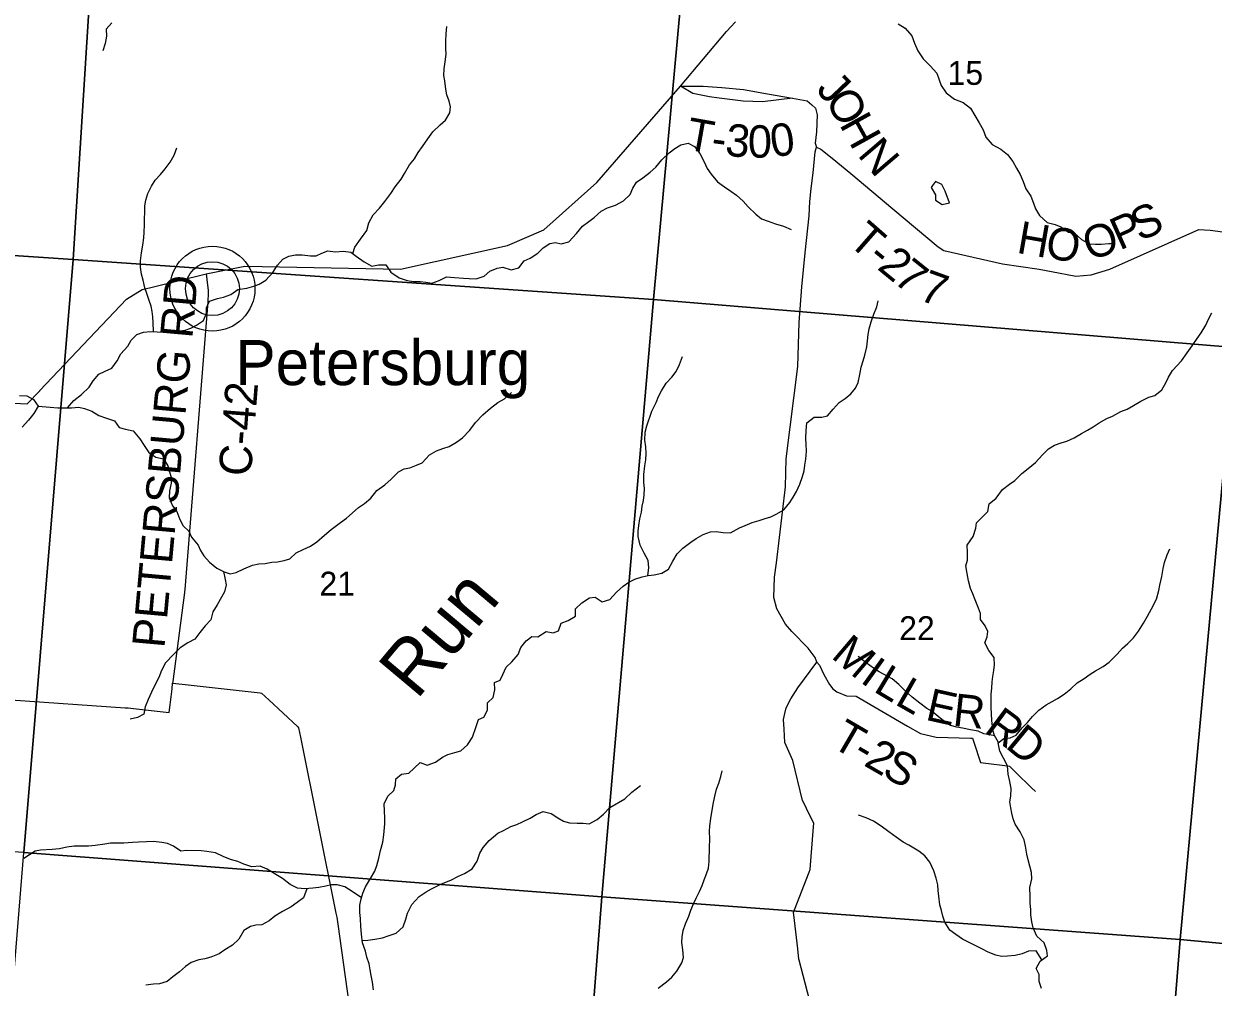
# Model space of a CAD drawing. Extents: x 1715311 to 2083412, y 146837 to 553079.
# Drawn here: x 1897277 to 1908281, y 354105 to 363016 of the extents above; entities that cross this region are included whole.
import ezdxf

# ---------------------------------------------------------------- set-up
doc = ezdxf.new("R2010")
doc.units = 0
for name, color, linetype in [('GM_X_County_Road', 7, 'Continuous'), ('GM_X_County_Road_Text', 7, 'Continuous'), ('GM_X_Minor_Lake', 7, 'Continuous'), ('GM_X_Minor_River', 7, 'Continuous'), ('GM_X_Minor_River_Text', 7, 'Continuous'), ('GM_X_Section', 7, 'Continuous'), ('GM_X_Section_Text', 7, 'Continuous'), ('GM_X_State_Route', 7, 'Continuous'), ('GM_X_Township_Road', 7, 'Continuous'), ('GM_X_Township_Road_Text', 7, 'Continuous'), ('GM_X_Township_ROW', 7, 'Continuous'), ('GM_X_Unincorporated', 7, 'Continuous'), ('GM_X_Unincorporated_Location', 7, 'Continuous'), ('GM_X_Unincorporated_Text', 7, 'Continuous')]:
    doc.layers.add(name, color=color, linetype=linetype)

msp = doc.modelspace()

# ---------------------------------------------------------------- linework, layer by layer
at = {"layer": 'GM_X_County_Road'}
msp.add_lwpolyline([(1898963, 360703), (1898969, 360652), (1898981, 360549), (1898984, 360524), (1898978, 360445), (1898773, 357859), (1898770, 357819), (1898762, 357755), (1898656, 356932), (1898654, 356916), (1898741, 356907), (1899464, 356828), (1899477, 356826), (1899543, 356764), (1899808, 356516), (1899819, 356505), (1899837, 356419), (1900165, 354791), (1900172, 354754), (1900181, 354688), (1900404, 353095)], dxfattribs=at)
at = {"layer": 'GM_X_Minor_Lake'}
for points in [[(1905685, 361520), (1905672, 361502), (1905712, 361433), (1905712, 361383), (1905774, 361345), (1905840, 361361)], [(1905840, 361361), (1905800, 361467), (1905770, 361529), (1905711, 361558), (1905685, 361520)]]:
    msp.add_lwpolyline(points, dxfattribs=at)
at = {"layer": 'GM_X_Minor_River'}
for points in [[(1898092, 363026), (1898038, 362966), (1898043, 362902), (1898031, 362834), (1898007, 362766)], [(1900320, 360890), (1900339, 360950), (1900391, 361024), (1900452, 361105), (1900470, 361175), (1900508, 361249), (1900568, 361311), (1900618, 361371), (1900673, 361447), (1900713, 361507), (1900769, 361579), (1900799, 361630), (1900845, 361710), (1900892, 361766), (1900926, 361824), (1900964, 361882), (1901014, 361952), (1901060, 362016), (1901128, 362080), (1901178, 362125), (1901219, 362193), (1901225, 362249), (1901211, 362299), (1901191, 362360), (1901180, 362412), (1901172, 362488), (1901164, 362538), (1901166, 362598), (1901174, 362664), (1901183, 362734), (1901181, 362786), (1901181, 362854), (1901185, 362924), (1901190, 362992)], [(1905366, 363016), (1905430, 362974), (1905494, 362903), (1905518, 362837), (1905547, 362767), (1905599, 362693), (1905663, 362627), (1905724, 362558), (1905746, 362496), (1905764, 362444), (1905809, 362376), (1905889, 362319), (1905967, 362287), (1906037, 362235), (1906076, 362167), (1906116, 362100), (1906154, 362036), (1906177, 361968), (1906237, 361898), (1906315, 361857), (1906377, 361807), (1906428, 361741), (1906462, 361681), (1906494, 361623), (1906522, 361556), (1906549, 361490), (1906593, 361422), (1906619, 361358), (1906638, 361304), (1906674, 361242), (1906744, 361179), (1906820, 361159), (1906872, 361137), (1906943, 361090), (1906999, 361080), (1907063, 361020), (1907135, 360982), (1907191, 360977), (1907244, 360977), (1907314, 360983), (1907366, 360983)], [(1897680, 359464), (1897741, 359531), (1897811, 359586), (1897882, 359654), (1897918, 359714), (1897970, 359776), (1898030, 359802), (1898090, 359832), (1898142, 359899), (1898176, 359963), (1898239, 360033), (1898269, 360089), (1898321, 360141), (1898383, 360163), (1898449, 360170), (1898511, 360168), (1898569, 360164), (1898639, 360172), (1898716, 360175), (1898770, 360183), (1898822, 360201), (1898874, 360227), (1898938, 360271), (1898967, 360339), (1898967, 360389), (1898995, 360451), (1899069, 360474), (1899123, 360486), (1899191, 360512), (1899257, 360558), (1899339, 360571), (1899405, 360589), (1899455, 360609), (1899517, 360643), (1899581, 360714), (1899624, 360784), (1899674, 360840), (1899728, 360866), (1899792, 360880), (1899852, 360880), (1899929, 360871), (1899983, 360871), (1900033, 360893), (1900091, 360915), (1900157, 360908), (1900235, 360912), (1900301, 360904), (1900353, 360866), (1900425, 360813), (1900496, 360775), (1900558, 360787), (1900626, 360787), (1900672, 360718), (1900750, 360666), (1900823, 360642), (1900881, 360633), (1900943, 360633), (1900997, 360627), (1901051, 360617), (1901121, 360641), (1901187, 360676), (1901261, 360670), (1901345, 360662), (1901397, 360659), (1901461, 360657), (1901535, 360683), (1901587, 360727), (1901657, 360757), (1901709, 360766), (1901785, 360740), (1901857, 360758), (1901907, 360822), (1901961, 360849), (1902033, 360893), (1902081, 360945), (1902143, 360985), (1902195, 360993), (1902249, 360982), (1902319, 361000), (1902389, 361076), (1902447, 361144), (1902503, 361186), (1902555, 361223), (1902620, 361283), (1902678, 361313), (1902750, 361337), (1902824, 361379), (1902886, 361436), (1902910, 361494), (1902946, 361550), (1903004, 361592), (1903072, 361644), (1903124, 361690), (1903181, 361757), (1903249, 361821), (1903299, 361863), (1903357, 361897), (1903425, 361911), (1903483, 361882), (1903532, 361816), (1903568, 361744)], [(1898476, 360169), (1898473, 360252), (1898471, 360304), (1898465, 360354), (1898456, 360405), (1898438, 360457), (1898416, 360521), (1898398, 360573), (1898381, 360645), (1898365, 360701), (1898357, 360765), (1898357, 360823), (1898366, 360897), (1898378, 360969), (1898388, 361035), (1898390, 361089), (1898392, 361155), (1898393, 361209), (1898395, 361277), (1898397, 361333), (1898405, 361383), (1898424, 361445), (1898458, 361515), (1898492, 361569), (1898542, 361621), (1898586, 361673), (1898632, 361737), (1898669, 361801), (1898693, 361869)], [(1903568, 361744), (1903600, 361678), (1903635, 361624), (1903695, 361555), (1903761, 361509), (1903819, 361469), (1903870, 361431), (1903932, 361376), (1903980, 361322), (1904048, 361256), (1904101, 361213), (1904165, 361189), (1904233, 361165), (1904307, 361143), (1904377, 361114)], [(1905043, 359897), (1905057, 359951), (1905078, 360027), (1905084, 360083), (1905090, 360141), (1905098, 360195), (1905117, 360259), (1905141, 360329), (1905169, 360397), (1905181, 360453)], [(1906294, 356367), (1906259, 356432), (1906243, 356482), (1906233, 356576), (1906230, 356634), (1906228, 356692), (1906228, 356816), (1906233, 356870), (1906235, 356928), (1906241, 356980), (1906251, 357034), (1906257, 357086), (1906256, 357154), (1906206, 357220), (1906168, 357291), (1906190, 357345), (1906197, 357395), (1906171, 357447), (1906127, 357505), (1906127, 357561), (1906109, 357611), (1906080, 357689), (1906058, 357743), (1906036, 357794), (1906018, 357864), (1906005, 357930), (1905991, 358002), (1906009, 358054), (1906009, 358126), (1906006, 358192), (1906060, 358274), (1906084, 358350), (1906092, 358400), (1906143, 358452), (1906197, 358505), (1906207, 358575), (1906273, 358629), (1906333, 358707), (1906397, 358757), (1906447, 358793), (1906510, 358856), (1906570, 358904), (1906638, 358958), (1906702, 359030), (1906758, 359084), (1906814, 359118), (1906874, 359141), (1906926, 359155), (1906996, 359185), (1907064, 359227), (1907118, 359258), (1907172, 359288), (1907226, 359324), (1907298, 359364), (1907350, 359388), (1907428, 359429), (1907484, 359451), (1907545, 359485), (1907613, 359525), (1907687, 359561), (1907741, 359578), (1907807, 359630), (1907843, 359694), (1907867, 359746), (1907903, 359810), (1907987, 359898), (1908040, 359973), (1908088, 360037), (1908132, 360105), (1908170, 360157), (1908214, 360227), (1908239, 360285), (1908267, 360341)], [(1900617, 355617), (1900617, 355667), (1900614, 355737), (1900612, 355801), (1900644, 355871), (1900700, 355923), (1900716, 355977), (1900719, 356031), (1900771, 356074), (1900839, 356086), (1900889, 356132), (1900945, 356184), (1901009, 356158), (1901085, 356185), (1901151, 356233), (1901201, 356257), (1901265, 356275), (1901321, 356291), (1901383, 356346), (1901427, 356418), (1901463, 356516), (1901484, 356580), (1901534, 356602), (1901566, 356666), (1901566, 356734), (1901620, 356786), (1901636, 356854), (1901633, 356922), (1901685, 356946), (1901709, 356998), (1901739, 357065), (1901791, 357113), (1901851, 357183), (1901874, 357247), (1901926, 357309), (1901978, 357349), (1902032, 357345), (1902110, 357396), (1902174, 357382), (1902224, 357402), (1902248, 357472), (1902314, 357496), (1902380, 357537), (1902382, 357605), (1902440, 357661), (1902510, 357705), (1902562, 357713), (1902628, 357669), (1902698, 357690), (1902760, 357760), (1902822, 357814), (1902874, 357852), (1902929, 357878), (1902999, 357901), (1903052, 357913), (1903108, 357919), (1903180, 357935), (1903242, 357972), (1903281, 358044), (1903321, 358114), (1903373, 358166), (1903447, 358222), (1903499, 358256), (1903561, 358291), (1903629, 358317), (1903683, 358319), (1903747, 358311), (1903815, 358308), (1903899, 358354), (1903951, 358374), (1904017, 358404), (1904081, 358423), (1904135, 358439), (1904189, 358457), (1904239, 358481), (1904309, 358519), (1904363, 358587), (1904395, 358638), (1904426, 358690), (1904458, 358758), (1904482, 358828), (1904496, 358880), (1904504, 358932), (1904513, 358990), (1904517, 359062), (1904515, 359124), (1904513, 359184), (1904516, 359254), (1904522, 359326), (1904590, 359376), (1904660, 359376), (1904712, 359390), (1904766, 359450), (1904822, 359513), (1904876, 359549), (1904928, 359593), (1904972, 359645), (1904995, 359699), (1905013, 359771), (1905025, 359839), (1905043, 359897)], [(1903049, 357912), (1903059, 357983), (1903053, 358051), (1903017, 358119), (1902978, 358192), (1902960, 358274), (1902960, 358324), (1902966, 358376), (1902977, 358438), (1902991, 358500), (1902999, 358554), (1903011, 358606), (1903015, 358660), (1903018, 358718), (1903014, 358772), (1903012, 358846), (1903024, 358926), (1903032, 358982), (1903035, 359040), (1903031, 359104), (1903023, 359164), (1903027, 359238), (1903042, 359296), (1903086, 359432), (1903126, 359512), (1903148, 359568), (1903177, 359620), (1903221, 359692), (1903271, 359748), (1903311, 359799), (1903343, 359863), (1903370, 359937)], [(1897238, 359579), (1897306, 359574), (1897368, 359540), (1897410, 359480), (1897370, 359412), (1897321, 359350), (1897263, 359284)], [(1897410, 359480), (1897521, 359469), (1897591, 359463), (1897647, 359463), (1897719, 359465), (1897787, 359470), (1897839, 359458), (1897907, 359434), (1897972, 359392), (1898042, 359369), (1898116, 359343), (1898160, 359281), (1898218, 359267), (1898288, 359250), (1898351, 359176), (1898389, 359116), (1898433, 359050), (1898498, 359007), (1898568, 358991), (1898610, 358927), (1898626, 358871), (1898640, 358821), (1898641, 358767), (1898625, 358695), (1898621, 358631), (1898653, 358558), (1898694, 358504), (1898720, 358432), (1898750, 358372), (1898805, 358322), (1898827, 358266), (1898889, 358195), (1898913, 358145), (1898942, 358095), (1898996, 358037), (1899064, 357982), (1899130, 357946), (1899186, 357928), (1899243, 357940), (1899314, 357975), (1899392, 358009), (1899452, 358021), (1899511, 358025), (1899571, 358035), (1899623, 358040), (1899685, 358052), (1899737, 358068), (1899797, 358122), (1899861, 358153), (1899928, 358185), (1899988, 358223), (1900058, 358285), (1900120, 358339), (1900206, 358402), (1900262, 358442), (1900316, 358490), (1900374, 358542), (1900430, 358578), (1900486, 358627), (1900543, 358699), (1900617, 358751), (1900677, 358803), (1900745, 358871), (1900795, 358900), (1900847, 358910), (1900911, 358932), (1900961, 358956), (1901031, 359030), (1901095, 359067), (1901155, 359089), (1901213, 359105), (1901281, 359145), (1901337, 359185), (1901404, 359256), (1901456, 359328), (1901524, 359400), (1901594, 359462), (1901664, 359512), (1901724, 359547), (1901790, 359607)], [(1907788, 357825), (1907806, 357903), (1907819, 357979), (1907829, 358033), (1907855, 358103), (1907881, 358159)], [(1899124, 357949), (1899141, 357876), (1899149, 357826), (1899133, 357762), (1899065, 357642), (1899026, 357576), (1899006, 357504), (1898956, 357446), (1898906, 357385), (1898858, 357325), (1898794, 357291), (1898722, 357245), (1898661, 357183), (1898587, 357106), (1898551, 357034), (1898527, 356968), (1898493, 356904), (1898458, 356834), (1898428, 356766), (1898400, 356698), (1898386, 356630), (1898330, 356600), (1898262, 356584)], [(1906694, 354094), (1906670, 354158), (1906670, 354224), (1906642, 354279), (1906679, 354347), (1906747, 354396), (1906743, 354446), (1906717, 354515), (1906648, 354577), (1906614, 354655), (1906602, 354711), (1906594, 354773), (1906593, 354823), (1906589, 354881), (1906587, 354943), (1906585, 355027), (1906602, 355107), (1906600, 355167), (1906584, 355224), (1906568, 355282), (1906558, 355334), (1906543, 355408), (1906531, 355468), (1906495, 355542), (1906450, 355612), (1906430, 355662), (1906418, 355715), (1906408, 355765), (1906400, 355821), (1906409, 355873), (1906413, 355943), (1906401, 356009), (1906383, 356075), (1906378, 356151), (1906340, 356223), (1906306, 356287), (1906293, 356366), (1906343, 356405), (1906403, 356411), (1906457, 356435), (1906513, 356503), (1906563, 356553), (1906609, 356608), (1906669, 356668), (1906737, 356718), (1906791, 356748), (1906841, 356776), (1906903, 356815), (1906964, 356865), (1907024, 356919), (1907086, 356961), (1907142, 356999), (1907192, 357031), (1907262, 357070), (1907318, 357110), (1907394, 357184), (1907442, 357242), (1907492, 357284), (1907543, 357335), (1907589, 357399), (1907635, 357473), (1907673, 357537), (1907711, 357605), (1907758, 357693), (1907778, 357773), (1907788, 357825)], [(1906260, 356429), (1906159, 356450), (1906107, 356474), (1906037, 356485), (1905962, 356501), (1905910, 356509), (1905852, 356525), (1905800, 356556), (1905736, 356608), (1905682, 356656), (1905631, 356682), (1905567, 356731), (1905497, 356787), (1905426, 356851), (1905372, 356905), (1905310, 356958), (1905190, 357022), (1905139, 357056), (1905069, 357105), (1904997, 357163)], [(1903146, 354096), (1903222, 354156), (1903272, 354199), (1903319, 354253), (1903365, 354329), (1903381, 354381), (1903375, 354451), (1903366, 354519), (1903368, 354571), (1903378, 354631), (1903398, 354691), (1903430, 354761), (1903449, 354819), (1903473, 354877), (1903497, 354929), (1903529, 354989), (1903553, 355045), (1903573, 355097), (1903594, 355155), (1903612, 355207), (1903618, 355269), (1903622, 355401), (1903623, 355473), (1903621, 355547), (1903625, 355597), (1903633, 355665), (1903646, 355743), (1903658, 355813), (1903672, 355883), (1903686, 355937), (1903707, 355993), (1903725, 356055), (1903739, 356107)], [(1900409, 354537), (1900459, 354541), (1900523, 354548), (1900595, 354562), (1900647, 354580), (1900721, 354604), (1900787, 354663), (1900812, 354733), (1900828, 354789), (1900866, 354871), (1900936, 354945), (1900998, 354987), (1901048, 355015), (1901104, 355044), (1901156, 355066), (1901228, 355096), (1901300, 355132), (1901354, 355158), (1901425, 355199), (1901471, 355271), (1901497, 355345), (1901527, 355397), (1901581, 355463), (1901661, 355529), (1901715, 355554), (1901784, 355592), (1901838, 355610), (1901892, 355634), (1901962, 355670), (1902016, 355703), (1902082, 355731), (1902155, 355713), (1902217, 355671), (1902271, 355640), (1902325, 355624), (1902395, 355622), (1902451, 355622), (1902507, 355617), (1902583, 355655), (1902641, 355705), (1902699, 355767), (1902839, 355846), (1902903, 355910), (1902981, 355970)], [(1906695, 354359), (1906643, 354441), (1906571, 354437), (1906515, 354415), (1906449, 354399), (1906377, 354392), (1906321, 354390), (1906269, 354402), (1906200, 354428), (1906142, 354459), (1906084, 354487), (1906024, 354517), (1905962, 354549), (1905901, 354592), (1905843, 354634), (1905799, 354708), (1905779, 354762), (1905766, 354814), (1905752, 354868), (1905744, 354947), (1905736, 355001), (1905734, 355051), (1905719, 355113), (1905697, 355181), (1905659, 355263), (1905612, 355321), (1905558, 355364), (1905464, 355418), (1905412, 355448), (1905347, 355492), (1905279, 355541), (1905209, 355595), (1905137, 355641), (1905070, 355672), (1904998, 355696)], [(1900512, 354080), (1900502, 354152), (1900492, 354214), (1900482, 354266), (1900471, 354320), (1900451, 354384), (1900437, 354439), (1900411, 354515), (1900402, 354595), (1900396, 354667), (1900392, 354739), (1900386, 354795), (1900385, 354863), (1900399, 354923), (1900413, 354975), (1900439, 355033), (1900483, 355109), (1900524, 355179), (1900542, 355231), (1900560, 355299), (1900578, 355369), (1900598, 355445), (1900609, 355513), (1900617, 355617)], [(1900402, 354933), (1900315, 354989), (1900247, 355034), (1900176, 355052), (1900124, 355052), (1900070, 355040), (1900006, 355027), (1899950, 355021), (1899878, 355015), (1899808, 355021), (1899740, 355056), (1899670, 355110), (1899609, 355148), (1899529, 355197), (1899463, 355225), (1899385, 355217), (1899311, 355243), (1899256, 355268), (1899188, 355286), (1899120, 355314), (1899050, 355349), (1898970, 355361), (1898918, 355367), (1898783, 355368), (1898729, 355364), (1898663, 355410), (1898607, 355434), (1898555, 355442), (1898477, 355453), (1898411, 355451), (1898339, 355445), (1898281, 355444), (1898202, 355436), (1898078, 355436), (1898026, 355427), (1897938, 355417), (1897876, 355411), (1897810, 355409), (1897742, 355408), (1897674, 355400), (1897608, 355384), (1897540, 355378), (1897430, 355374)], [(1897430, 355374), (1897382, 355363), (1897278, 355296)], [(1899894, 355016), (1899866, 354933), (1899807, 354889), (1899749, 354847), (1899671, 354804), (1899599, 354762), (1899547, 354718), (1899479, 354682), (1899425, 354679), (1899373, 354665), (1899313, 354631), (1899267, 354549), (1899209, 354493), (1899137, 354450), (1899083, 354414), (1899007, 354384), (1898951, 354368), (1898897, 354358), (1898825, 354335), (1898773, 354297), (1898718, 354247), (1898656, 354201), (1898602, 354159), (1898532, 354136), (1898478, 354134), (1898406, 354124)]]:
    msp.add_lwpolyline(points, dxfattribs=at)
at = {"layer": 'GM_X_Section'}
for points in [[(1892735, 366736), (1898082, 366380), (1897732, 360835), (1892273, 361204)], [(1898082, 366380), (1903608, 365982), (1903104, 360466), (1897732, 360835)], [(1903608, 365982), (1908913, 365453), (1908481, 360021), (1903104, 360466)], [(1897732, 360835), (1897276, 355350), (1891838, 355685), (1892273, 361204)], [(1897732, 360835), (1903104, 360466), (1902626, 354942), (1897276, 355350)], [(1903104, 360466), (1908481, 360021), (1907976, 354545), (1902626, 354942)], [(1908481, 360021), (1913861, 359484), (1913462, 354034), (1907976, 354545)], [(1902626, 354942), (1902187, 349333), (1896827, 349829), (1897276, 355350)], [(1907976, 354545), (1907523, 348954), (1902187, 349333), (1902626, 354942)], [(1913462, 354034), (1912974, 348592), (1907523, 348954), (1907976, 354545)]]:
    msp.add_lwpolyline(points, close=True, dxfattribs=at)
at = {"layer": 'GM_X_State_Route'}
for points in [[(1897425, 359623), (1898226, 360468), (1898372, 360557), (1898452, 360577), (1898963, 360703), (1899321, 360774), (1900763, 360747), (1901751, 360964), (1902088, 361111), (1902577, 361549), (1903353, 362439), (1903779, 362944), (1903860, 363033)], [(1897009, 359532), (1897057, 359514), (1897309, 359500), (1897424, 359622), (1897425, 359623)]]:
    msp.add_lwpolyline(points, dxfattribs=at)
at = {"layer": 'GM_X_Township_Road'}
for points in [[(1903353, 362439), (1903563, 362440), (1903736, 362426), (1903936, 362408), (1904156, 362368), (1904389, 362327), (1904523, 362302), (1904569, 362267), (1904603, 362234), (1904617, 362174), (1904610, 362018), (1904600, 361911), (1904610, 361876), (1904650, 361856), (1904756, 361774), (1904929, 361632), (1905318, 361304), (1905737, 360953), (1905788, 360918), (1906332, 360796), (1906670, 360745), (1906784, 360724), (1907009, 360680), (1907152, 360695), (1907324, 360746), (1908148, 361112), (1908254, 361107), (1908371, 361092)], [(1904389, 362327), (1904112, 362293), (1903931, 362299), (1903711, 362327), (1903620, 362341), (1903467, 362371), (1903353, 362439)], [(1904482, 355832), (1904391, 356203), (1904319, 356368), (1904312, 356492), (1904307, 356580), (1904317, 356637), (1904329, 356688), (1904374, 356771), (1904439, 356873), (1904613, 357111), (1904598, 357155), (1904534, 357241), (1904384, 357395), (1904323, 357463), (1904243, 357606), (1904217, 357710), (1904223, 357898), (1904240, 358030), (1904324, 358733), (1904331, 358992), (1904438, 359846), (1904449, 360254), (1904474, 360582), (1904505, 360897), (1904543, 361240), (1904550, 361373), (1904561, 361492), (1904579, 361636), (1904597, 361832), (1904610, 361876)], [(1904613, 357111), (1904640, 357084), (1904679, 356998), (1904731, 356905), (1904762, 356866), (1904798, 356837), (1904887, 356801), (1904978, 356796), (1905452, 356519), (1905573, 356452), (1905719, 356417), (1906040, 356409), (1906053, 356409), (1906081, 356325), (1906113, 356230), (1906129, 356182), (1906179, 356176), (1906379, 356152), (1906395, 356150), (1906456, 356091), (1906601, 355950), (1906638, 355915)], [(1898216, 356690), (1898243, 356688), (1898293, 356682), (1898593, 356649), (1898622, 356646), (1898630, 356717), (1898648, 356866), (1898654, 356916)], [(1904582, 353845), (1904451, 354356), (1904448, 354365), (1904437, 354460), (1904401, 354775), (1904398, 354796), (1904429, 354875), (1904543, 355170), (1904553, 355195), (1904558, 355273), (1904582, 355589), (1904585, 355623), (1904553, 355687), (1904483, 355829), (1904482, 355832)]]:
    msp.add_lwpolyline(points, dxfattribs=at)
at = {"layer": 'GM_X_Township_ROW'}
msp.add_lwpolyline([(1897067, 356765), (1897157, 356762), (1898216, 356690)], dxfattribs=at)
at = {"layer": 'GM_X_Unincorporated'}
for radius in [393, 249]:
    msp.add_circle((1899022, 360566), radius, dxfattribs=at)
at = {"layer": 'GM_X_Unincorporated_Location'}
msp.add_line((1899022, 360566), (1899022, 360566), dxfattribs=at)

# ---------------------------------------------------------------- texts
at = {"layer": 'GM_X_County_Road_Text'}
for s, rotation, p in [('PETERSBURG RD', 84.8384, (1898577, 357236)), ('C-42', 85.522, (1899377, 358824))]:
    msp.add_text(s, height=300, rotation=rotation, dxfattribs=at).set_placement(p)
at = {"layer": 'GM_X_Minor_River_Text'}
msp.add_text('Run', height=500, rotation=50.0025, dxfattribs=at).set_placement((1900911, 356755))
at = {"layer": 'GM_X_Section_Text'}
for s, p in [('15', (1905824, 362451)), ('21', (1900012, 357727)), ('22', (1905376, 357315))]:
    msp.add_text(s, height=221, rotation=0, dxfattribs=at).set_placement(p)
at = {"layer": 'GM_X_Township_Road_Text'}
for s, rotation, p in [('J', 313.5267, (1904598, 362398)), ('O', 300.8226, (1904684, 362310)), ('H', 298.9067, (1904818, 362085)), ('T', 349.9416, (1903391, 361856)), ('3', 354.0953, (1903758, 361798)), ('0', 0.1323, (1903976, 361777)), ('0', 7.5142, (1904203, 361781)), ('-', 352.6642, (1903628, 361815)), ('N', 310.4441, (1904983, 361800)), ('S', 23.9654, (1907601, 361000)), ('T', 318.7786, (1904892, 360986)), ('H', 350.0454, (1906454, 360899)), ('O', 18.3366, (1907135, 360822)), ('P', 24.1545, (1907416, 360917)), ('O', 350.7057, (1906718, 360853)), ('-', 320.509, (1905068, 360832)), ('2', 320.5671, (1905163, 360753)), ('7', 321.3798, (1905310, 360633)), ('7', 340.0877, (1905547, 360466)), ('M', 319.6983, (1904737, 357159)), ('I', 324.2915, (1905006, 356932)), ('L', 328.9842, (1905128, 356846)), ('L', 330.1665, (1905326, 356727)), ('E', 347.4087, (1905610, 356580)), ('R', 353.8684, (1905865, 356525)), ('R', 323.4759, (1906153, 356472)), ('T', 329.6911, (1904736, 356337)), ('D', 320.4458, (1906348, 356328)), ('-', 329.7624, (1904931, 356224)), ('2', 330.0043, (1905038, 356161)), ('S', 331.2833, (1905205, 356065))]:
    msp.add_text(s, height=300, rotation=rotation, dxfattribs=at).set_placement(p)
at = {"layer": 'GM_X_Unincorporated_Text'}
msp.add_text('Petersburg', height=417, rotation=0, dxfattribs=at).set_placement((1899235, 359674))

doc.saveas('drawing.dxf')
